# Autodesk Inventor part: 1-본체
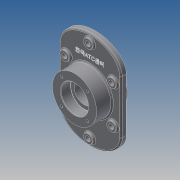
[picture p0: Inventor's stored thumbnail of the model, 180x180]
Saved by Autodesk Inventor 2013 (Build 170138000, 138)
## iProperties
Created: 2015-02
Part Number: 1-본체
Material: Generic
Document SubType Name: Modeling
Designer: kb543
Density: 1 g/cm^3
Author: kb543
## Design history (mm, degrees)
sketch "스케치1" dims "d74" = 50
  geometry: L1 (-70, 60)-(-70, -60); L2 (70, 60)-(70, -60); L3 (-70, 60)-(70, 60); L4 (-70, -60)-(70, -60); 5 further points; 2 other entities
  constraints: 8 end point, 3 horizontal alignment, 3 midpoint, 3 vertical, 2 perpendicular, 2 vertical alignment, 1 horizontal, 9 other
  dimensions: "d3" = 120 distance between parallel lines of L4 L3; "d5" = 140 distance between parallel lines of L2 L1; "d73" = 50 distance of point (0, 110) point (0, 60)
extrude "돌출1" new body sketch "스케치1" stored distance "d6" = 12; taper "d7" = 0 deg
sketch "스케치3"
  geometry: C1 r 50 at (0, 0); 1 further point
  constraints: 1 centre point, 1 coincident
  dimensions: "d10" = 100 diameter of C1
extrude "돌출2" join sketch "스케치3" distance "d12" = 23; taper "d13" = 0 deg
node "작업 평면1"
sketch "스케치4"
  geometry: C1 r 50 at (0, 0); 1 further point
  constraints: 1 centre point, 1 coincident
  dimensions: "d15" = 100 diameter of C1
extrude "돌출3" join sketch "스케치4" stored distance "d17" = 23; taper "d18" = 0 deg
sketch "스케치5"
  geometry: L1 (-41, -50)-(-41, 50) reference; L2 (-41, 31)-(-19, 31); L3 (-19, 31)-(-19, 22.5); L4 (-19, 22.5)-(7, 22.5); L5 (7, 22.5)-(7, 31); L6 (7, 31)-(29, 31); L7 (-41, 0)-(29, 0); L8 (29, -50)-(29, 50) reference; 1 further point
  constraints: 12 end point, 2 midpoint, 2 perpendicular, 2 point on line
  dimensions: "d19" = 62 diameter of L2 L7; "d21" = 45 diameter of L4 L7; "d22" = 62 diameter of L6 L7 (= d19); "d23" = 22 distance between parallel lines of L1 L3; "d24" = 22 distance between parallel lines of L8 L5
revolve "회전1" sketch "스케치5" stored, may be unused: angle "d25" = 90 deg
sketch "스케치6"
  geometry: L1 (70, -60)-(70, 60) reference; L2 (-70, 60)-(-70, -60) reference; L3 (-70, 0)-(70, 0); L4 (-53, 60)-(-53, -60); L5 (53, -60)-(53, 60); C1 r 50 at (0, 0) reference; C2 r 10 at (0, 93); C3 r 10 at (0, -93); C4 r 10 at (53, 42.733); C5 r 10 at (53, -42.733); C6 r 10 at (-53, 42.733); C7 r 10 at (-53, -42.733); 3 further points; 2 other entities
  constraints: 6 centre point, 6 end point, 3 equal radius, 3 midpoint, 3 parallel, 2 point on line, 2 vertical alignment, 1 coincident, 1 perpendicular, 12 other
  dimensions: "d75" = 17 distance between parallel lines of L1 L5; "d76" = 85.46667 distance of C5.centre C4.centre; "d77" = 85.46667 distance of C7.centre C6.centre (= d76); "d78" = 20 diameter of C6
extrude "돌출4" join sketch "스케치6" distance "d38" = 5; taper "d39" = 0 deg
sketch "스케치8"
  geometry: L1 (0, 0)-(0, 41); L2 (0, 0)-(-28.991, 28.991); C1 r 50 at (0, 0) reference; A1 r 41 centre (0, 0) between (-28.991, 28.991) and (0, 41); 1 further point
  constraints: 4 end point, 2 coincident, 2 point on circle, 1 centre point, 1 vertical
  dimensions: "d47" = 82 diameter of A1; "d49" = 45 deg angle of L1 L2
hole "구멍2" sketch "스케치8" at (-28.991, 28.991) diameter "d51" = 5.459; stored, may be unused: countersink angle "d55" = 90 deg, drill point angle "d57" = 118 deg; dims "d52" = 10, "d53" = 4, "d54" = 2, "d56" = 13
node "작업 평면2"
sketch "스케치9"
  geometry: C1 r 50 at (0, 0) reference; 1 further point
  constraints: 1 vertical alignment, 1 other
  dimensions: "d61" = 65 distance of point (0, 65) C1.centre
feature "엠보싱1" sketch "스케치9" dims "d3" = 120, "d5" = 140, "d62" = 1, "d63" = 0, "d73" = 50, "d74" = 50
fillet "모깎기1" dims "d64" = 3, "d65" = 0.3
chamfer "모따기1" distance "d67" = 1; stored, may be unused: second distance "d68" = 2, angle "d69" = 45 deg
chamfer "모따기2" distance "d70" = 1; stored, may be unused: second distance "d71" = 2, angle "d72" = 45 deg
sketch "스케치10"
  geometry: C1 r 10 at (0, 0) reference; C2 r 10 at (53, 50.267) reference; C3 r 10 at (106, 0) reference; C4 r 10 at (106, -85.467) reference; C5 r 10 at (0, -85.467) reference; C6 r 10 at (53, -135.733) reference; 1 further point
hole "구멍3" sketch "스케치10" at (53, 50.267), (0, 0), (0, -85.467), (53, -135.733), (106, -85.467), (106, 0) diameter "d81" = 11; stored, may be unused: countersink angle "d85" = 90 deg, drill point angle "d87" = 118 deg; dims "d82" = 10, "d83" = 4, "d84" = 2, "d86" = 13
fillet "모깎기3" dims "d88" = 3
node "솔리드1"
pattern_circular "원형 패턴1" dims angle "d59" = 360 deg
mirror "대칭1"
node "투영된 루프1"
node "투영된 루프2"
node "투영된 루프3"
node "투영된 루프4"
other parameters: "d33" = 83.35367
